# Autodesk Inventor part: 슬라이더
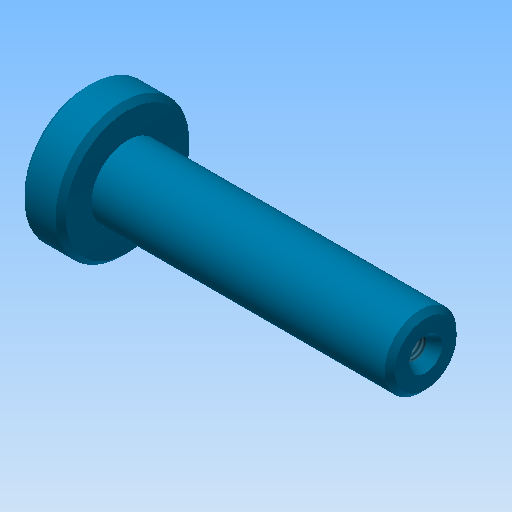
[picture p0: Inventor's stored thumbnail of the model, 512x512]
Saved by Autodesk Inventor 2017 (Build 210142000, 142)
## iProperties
Created: 2019-01
Part Number: 슬라이더
Material: 강철, 연강
Document SubType Name: Modeling
Designer: mduedu
Density: 7.86 g/cm^3
Appearance: 하늘색 중간
Mass: 101.006 g
Surface Area: 43.3118 cm^2
Volume: 12.8506 cm^3
Author: mduedu
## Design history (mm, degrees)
sketch "스케치1"
  geometry: L1 (0, 0)-(8, 0); L2 (8, 0)-(8, 13); L3 (8, 13)-(0, 13); L4 (0, 13)-(0, 0); L5 (8, 0)-(66, 0); L6 (66, 0)-(66, 7); L7 (66, 7)-(8, 7); L8 (8, 7)-(8, 0)
  constraints: 16 end point, 4 parallel, 2 horizontal, 2 perpendicular
  dimensions: "d0" = 66 distance between parallel lines of L6 L4; "d2" = 8 distance of L2.end L3.end; "d3" = 26 diameter of L3 L1; "d4" = 14 diameter of L7 L5
revolve "회전1" sketch "스케치1" stored, may be unused: angle "d5" = 90 deg
chamfer "모따기1" distance "d6" = 1; stored, may be unused: second distance "d7" = 2, angle "d8" = 45 deg
hole "구멍1" diameter "d14" = 4.134; stored, may be unused: countersink angle "d18" = 60 deg, drill point angle "d20" = 118 deg; dims "d15" = 12, "d16" = 6.3, "d17" = 2, "d19" = 15, "d26" = 10, "d27" = 10
chamfer "모따기4" distance "d24" = 1; stored, may be unused: second distance "d25" = 2, angle "d28" = 30 deg
sketch "스케치2"
  geometry: L1 (66, 2.067)-(66, -2.067) reference; L2 (66, 0)-(64, 0); L3 (64, 0)-(64, 2.067); L4 (66, 3.222)-(66, 0); L5 (66, 3.222)-(64, 2.067); L6 (51, 2.067)-(66, 2.067) reference; 1 further point
  constraints: 8 end point, 1 horizontal, 1 midpoint, 1 parallel, 1 perpendicular, 1 point on line
  dimensions: "d29" = 2 horizontal distance of L4.start L3.end; "d31" = 30 deg angle of L2 L5
revolve "회전2" sketch "스케치2" stored, may be unused: angle "d33" = 90 deg
node "솔리드1"
